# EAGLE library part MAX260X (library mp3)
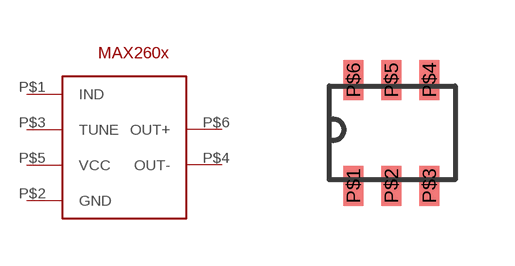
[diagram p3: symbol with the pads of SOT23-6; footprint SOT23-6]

Designator prefix -

## MAX260X  [SOT23-6]
P$1  IND
P$2  GND
P$3  TUNE
P$4  OUT-
P$5  VCC
P$6  OUT+

## Footprint SOT23-6 (pad centres in mm)
smd 0.5 x 1: P$1 0.3,0.5; P$2 1.25,0.5; P$3 2.2,0.5; P$4 2.2,3.15; P$5 1.25,3.15; P$6 0.3,3.15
